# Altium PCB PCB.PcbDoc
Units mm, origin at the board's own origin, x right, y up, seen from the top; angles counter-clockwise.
Board outline 90 x 70 mm, 2 copper layers (Top Layer, Bottom Layer); 87 components, 38 nets, 231 pads, 138 vias.
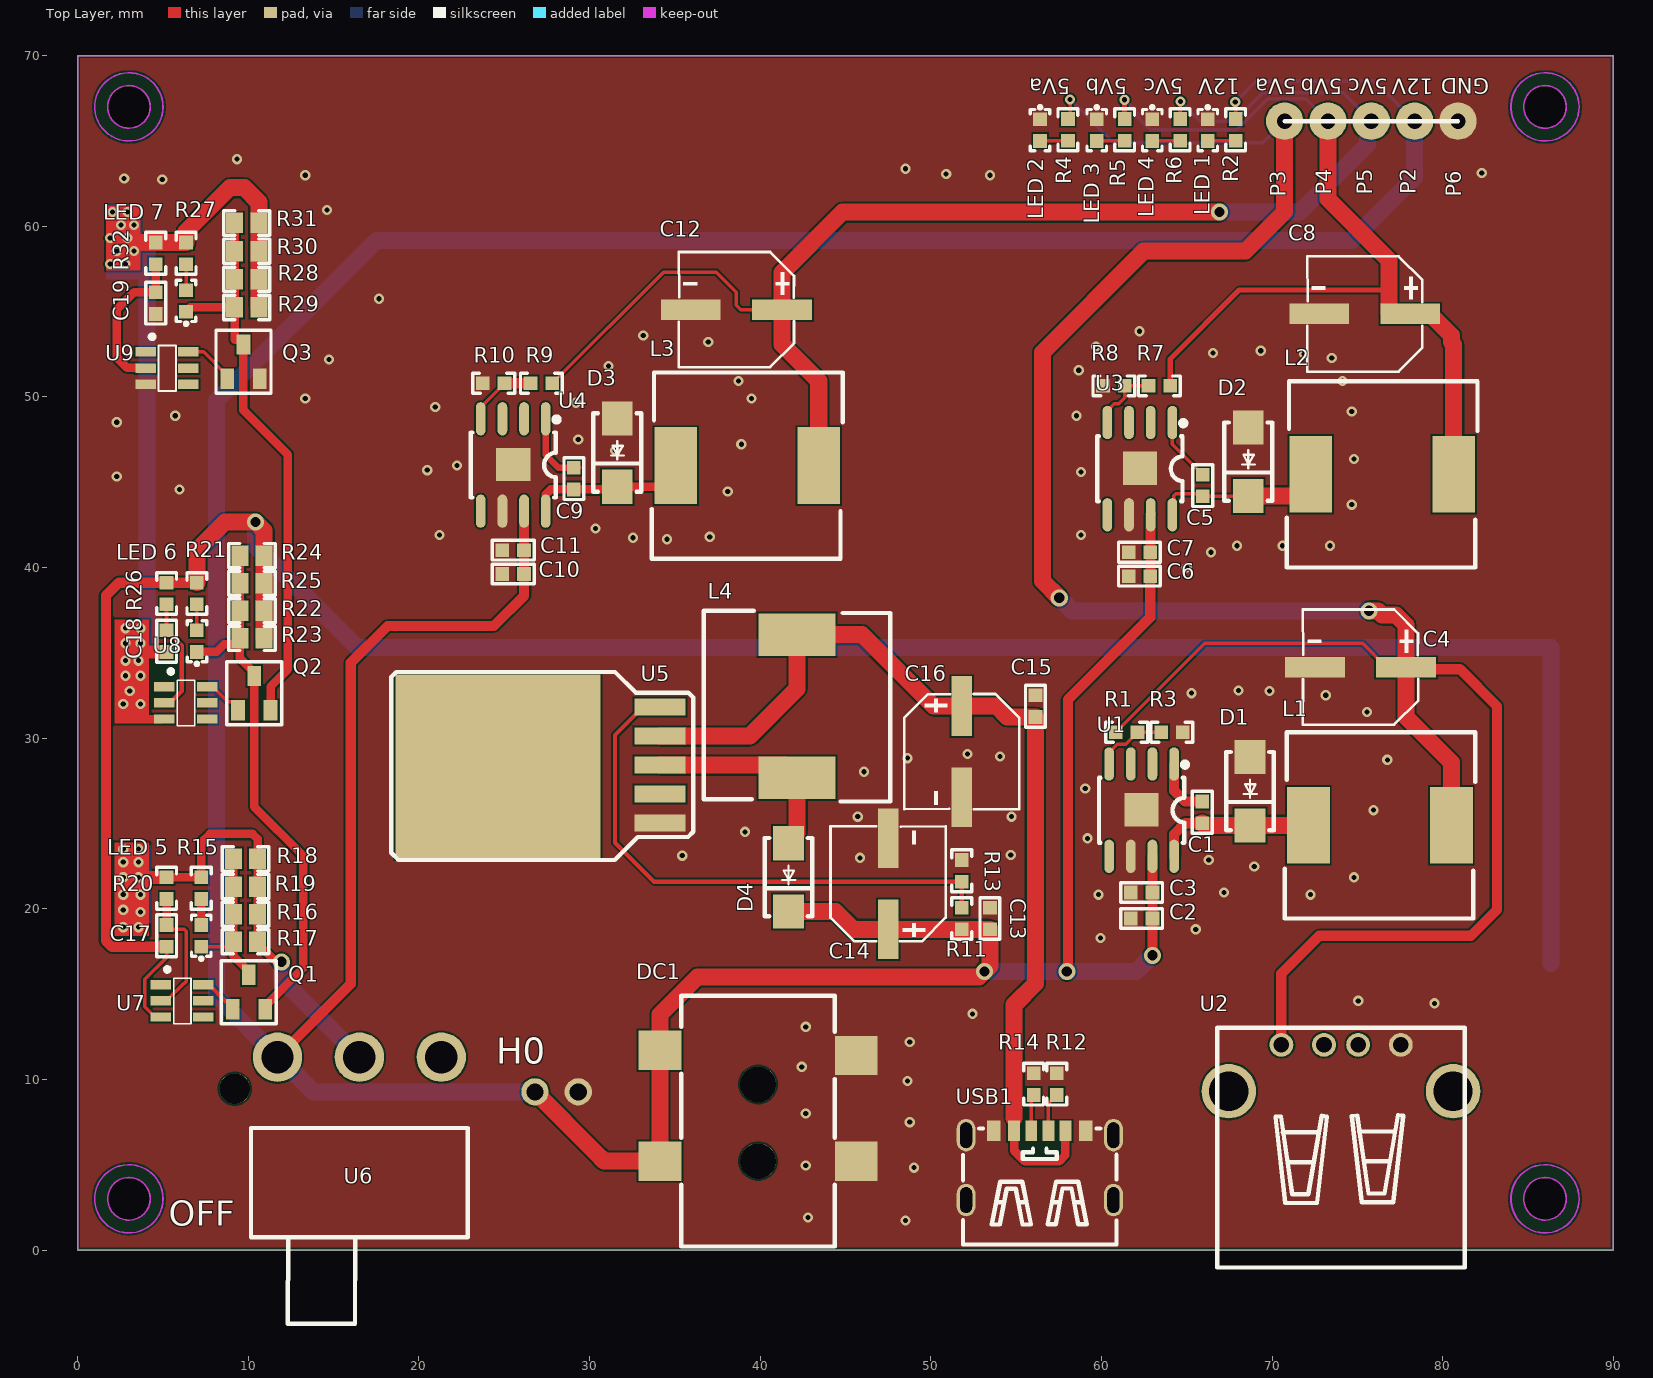
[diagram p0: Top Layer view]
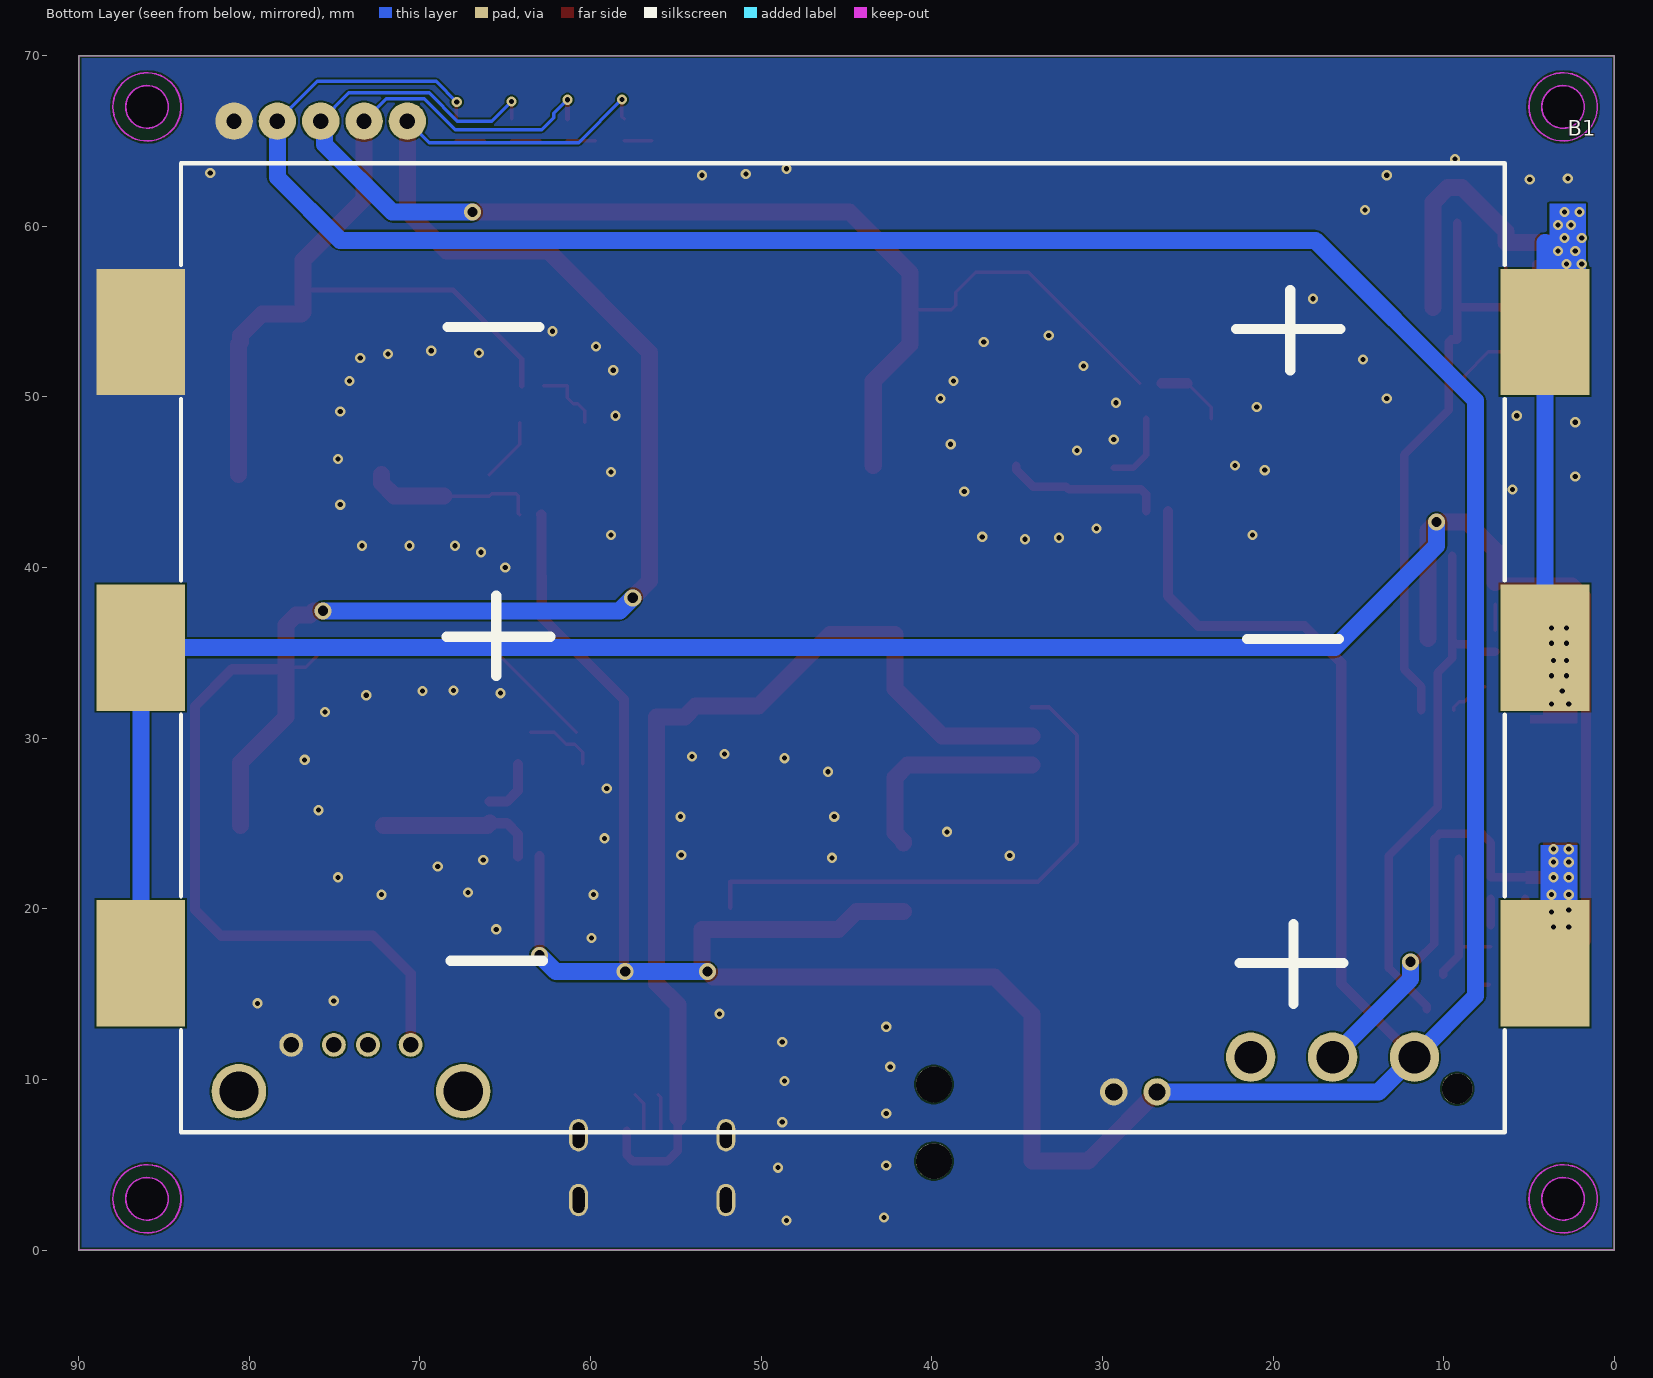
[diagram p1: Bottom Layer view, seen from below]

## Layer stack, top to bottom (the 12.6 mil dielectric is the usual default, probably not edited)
Top Solder: solder mask 0.0102, Solder Resist, Dk 3.5
Top Layer: signal copper 0.0356
Dielectric 1: dielectric 0.32, FR-4, Dk 4.8
Bottom Layer: signal copper 0.0356
Bottom Solder: solder mask 0.0102, Solder Resist, Dk 3.5

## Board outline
0,0 0,70 90,70 90,0
cut-out: 84.75,3 ccw(c86,3) 86,1.75 ccw(c86,3) 87.25,3 ccw(c86,3) 86,4.25 ccw(c86,3)
cut-out: 1.75,3 ccw(c3,3) 3,1.75 ccw(c3,3) 4.25,3 ccw(c3,3) 3,4.25 ccw(c3,3)
cut-out: 84.75,67 ccw(c86,67) 86,65.75 ccw(c86,67) 87.25,67 ccw(c86,67) 86,68.25 ccw(c86,67)
cut-out: 3,65.75 cw(c3,67) 1.75,67 cw(c3,67) 3,68.25 cw(c3,67) 4.25,67 cw(c3,67)

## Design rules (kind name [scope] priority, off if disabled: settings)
Clearance [All] p1: gap=0.1 ignorepadtopadclearanceinfootprint=FALSE except(0: Arc-Hole Track-Hole SMDPad-Hole THPad-Hole Via-Hole Fill-Hole Poly-Hole Region-Hole Text-Hole; 0.102: Arc-Arc Arc-Track Arc-SMDPad Arc-THPad Track-Track Track-SMDPad Track-THPad SMDPad-SMDPad SMDPad-THPad THPad-THPad; 0.127: Arc-Via Track-Via SMDPad-Via SMDPad-Text THPad-Via Via-Via; 0.254: Arc-Text Track-Text THPad-Text Via-Text Fill-Text Poly-Text Region-Text Text-Text)
ComponentClearance [All] p1 off: gap=0 collisioncheckmode=3 verticalgap=0 showdistances=TRUE
HoleSize [All] p1: absolutevalues=TRUE maxlimit=30 minlimit=0.025 maxpercent=80.000 minpercent=20.000
HoleToHoleClearance [All] p1: gap=0.152 allowstackedmicrovias=TRUE
MinimumSolderMaskSliver [All] p1: minsoldermaskwidth=0
PlaneClearance [All] p1: clearance=0.254
PlaneConnect [All] p1: planeconnectstyle=Direct reliefexpansion=0.508 reliefentries=4 reliefconductorwidth=0.254 reliefairgap=0.254
PolygonConnect [All] p1: connectstyle=Direct reliefconductorwidth=0.254 reliefentries=4 polygonreliefangle="90 Angle" airgapwidth=0.254
RoutingVias [All] p1: holewidth=0.711 width=1.27 viastyle="Through Hole" minholewidth=0.3 minwidth=0.5 maxholewidth=30 maxwidth=30
SilkToSilkClearance [All] p1: silktosilkclearance=0
SilkToSolderMaskClearance [IsPad] p1: minsilkscreentomaskgap=0 clearancetoexposedcopper=TRUE
SolderMaskExpansion [All] p1: expansion=0.102 istentingtop=FALSE
Width [All] p1: maxlimit=5 minlimit=0.1 preferedwidth=0.254
22 further rules are at their usual default settings.

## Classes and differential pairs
component class Sheet1-MCU: C1 C2 C3 C4 C5 C6 C7 C8 C9 C10 C11 C12 C13 C14 C15 C16 D1 D2 D3 D4 DC1 H0 L1 L2 L3 L4 "LED 1" "LED 2" "LED 3" "LED 4" P2 P3 P4 P5 P6 R1 R2 R3 R4 R5 R6 R7 R8 R9 R10 R11 R12 R13 R14 U1 U2 U3 U4 U5 U6 USB1
component class Sheet2-bms: B1 C17 C18 C19 "LED 5" "LED 6" "LED 7" Q1 Q2 Q3 R15 R16 R17 R18 R19 R20 R21 R22 R23 R24 R25 R26 R27 R28 R29 R30 R31 R32 U7 U8 U9

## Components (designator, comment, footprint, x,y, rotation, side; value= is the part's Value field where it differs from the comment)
B1 "18650-box-3S" BAT-SMD_BH-18650-B5BA016 45.212,35.306 r0 bottom locked
C1 "0.01uf" CC1608-0603 65.913,25.654 r270 top
C2 "4.7uF 50V" CC1608-0603 62.357,19.431 r180 top
C3 "4.7uF 50V" CC1608-0603 62.357,20.955 r180 top
C4 "16V 220uF" CAP-SMD_D6.3 75.184,34.163 r180 top
C5 "0.01uf" CC1608-0603 65.938,44.806 r270 top
C6 "4.7uF 50V" CC1608-0603 62.23,39.497 r180 top
C7 "4.7uF 50V" CC1608-0603 62.23,40.894 r180 top
C8 "16V 220uF" CAP-SMD_D6.3 75.441,54.864 r180 top
C9 "0.01uf" CC1608-0603 29.083,45.212 r270 top
C10 "4.7uF 50V" CC1608-0603 25.527,39.624 r180 top
C11 "4.7uF 50V" CC1608-0603 25.527,41.021 r180 top
C12 "16V 220uF" CAP-SMD_D6.3 38.608,55.118 r180 top
C13 "100NF" CC1608-0603 53.467,19.431 r270 top
C14 "16V 220uF" CAP-SMD_D6.3 47.498,21.463 r90 top
C15 "100NF" CC1608-0603 56.134,31.877 r270 top
C16 "16V 220uF" CAP-SMD_D6.3 51.816,29.21 r270 top
C17 "100NF" CC1608-0603 5.207,18.415 r90 top
C18 "100NF" CC1608-0603 5.207,35.687 r90 top
C19 "100NF" CC1608-0603 4.572,55.499 r90 top
D1 "B340A" "DO-214 AA" 68.707,26.892 r90 top
D2 "B340A" "DO-214 AA" 68.605,46.203 r90 top
D3 "B340A" "DO-214 AA" 31.623,46.736 r90 top
D4 "SS56" "DO-214 AA" 41.656,21.844 r90 top
DC1 "DC-2.1" DC-IN-SMD_DC-050-25A 39.878,8.457 r180 top
H0 "Header_2P_Curved" Header_2_54_2PW 26.797,9.271 r0 top
L1 "22UH" Inductor-1040 72.136,24.892 r90 top
L2 "22UH" Inductor-1040 72.263,45.466 r90 top
L3 "22UH" Inductor-1040 35.052,45.974 r90 top
L4 "47UH" Inductor-1040 42.164,36.068 r0 top
"LED 1" "LED 0603" "LED 0603" 66.232,65.64 r90 top
"LED 2" "LED 0603" "LED 0603" 56.404,65.64 r90 top
"LED 3" "LED 0603" "LED 0603" 59.726,65.64 r90 top
"LED 4" "LED 0603" "LED 0603" 62.979,65.64 r90 top
"LED 5" "LED 0603" "LED 0603" 7.239,18.415 r270 top
"LED 6" "LED 0603" "LED 0603" 6.985,35.687 r270 top
"LED 7" "LED 0603" "LED 0603" 6.35,55.626 r270 top
P2 "pogopin" pogopin 78.359,66.167 r0 top
P3 "pogopin" pogopin 70.739,66.167 r0 top
P4 "pogopin" pogopin 73.279,66.167 r0 top
P5 "pogopin" pogopin 75.819,66.167 r0 top
P6 "pogopin" pogopin 80.899,66.167 r0 top
Q1 "SI2302" SOT-23 9.083,14.109 r0 top
Q2 "SI2302" SOT-23 9.398,31.623 r0 top
Q3 "SI2302" SOT-23 8.763,51.054 r0 top
R1 "10K 1%" CR1608-0603 61.484,30.353 r180 top
R2 "1K" CR1608-0603 67.867,65.659 r270 top
R3 "3.24K 1%" CR1608-0603 64.135,30.353 r180 top
R4 "1K" CR1608-0603 58.039,65.659 r270 top
R5 "1K" CR1608-0603 61.362,65.659 r270 top
R6 "1K" CR1608-0603 64.615,65.659 r270 top
R7 "10K 1%" CR1608-0603 63.398,50.648 r0 top
R8 "3.24K 1%" CR1608-0603 60.731,50.648 r0 top
R9 "10K 1%" CR1608-0603 27.178,50.8 r0 top
R10 "3.24K 1%" CR1608-0603 24.384,50.8 r0 top
R11 "88.7K" CR1608-0603 51.816,19.431 r270 top
R12 "5.1K" CR1608-0603 57.389,9.724 r90 top
R13 "10K" CR1608-0603 51.816,22.225 r270 top
R14 "5.1K" CR1608-0603 56.028,9.724 r90 top
R15 "1K" CR1608-0603 7.239,21.209 r270 top
R16 "120R 1/8W" CR2012-0805 9.837,19.684 r180 top
R17 "120R 1/8W" CR2012-0805 9.837,18.065 r180 top
R18 "120R 1/8W" CR2012-0805 9.837,22.922 r180 top
R19 "120R 1/8W" CR2012-0805 9.837,21.303 r180 top
R20 "100R" CR1608-0603 5.207,21.209 r270 top
R21 "1K" CR1608-0603 6.985,38.481 r270 top
R22 "120R 1/8W" CR2012-0805 10.218,37.464 r180 top
R23 "120R 1/8W" CR2012-0805 10.218,35.845 r180 top
R24 "120R 1/8W" CR2012-0805 10.218,40.702 r180 top
R25 "120R 1/8W" CR2012-0805 10.218,39.083 r180 top
R26 "100R" CR1608-0603 5.207,38.481 r270 top
R27 "1K" CR1608-0603 6.35,58.42 r270 top
R28 "120R 1/8W" CR2012-0805 9.906,56.896 r180 top
R29 "120R 1/8W" CR2012-0805 9.906,55.245 r180 top
R30 "120R 1/8W" CR2012-0805 9.906,58.547 r180 top
R31 "120R 1/8W" CR2012-0805 9.906,60.198 r180 top
R32 "100R" CR1608-0603 4.572,58.42 r270 top
U1 "TPS5430DDAR" SOIC-8-E 62.357,25.781 r180 top
U2 "USB2.0-A" USB2.0-A 74.041,10.668 r0 top
U3 "TPS5430DDAR" SOIC-8-E 62.255,45.796 r180 top
U4 "TPS5430DDAR" SOIC-8-E 25.527,46.012 r180 top
U5 "XL6019E1" TO-263-5 34.136,25.019 r90 top
U6 "HX SS12D10G4" SW-TH_3P-SS12D06 16.51,11.303 r0 top
U7 "HY2213-BB3A" SOT23-6 6.136,14.666 r270 top
U8 "HY2213-BB3A" SOT23-6 6.35,32.131 r270 top
U9 "HY2213-BB3A" SOT23-6 5.247,51.75 r270 top
USB1 "TYPE_C_SMD_6P" TYPE-C-SMD_TYPE-C-6P 56.388,4.953 r0 top

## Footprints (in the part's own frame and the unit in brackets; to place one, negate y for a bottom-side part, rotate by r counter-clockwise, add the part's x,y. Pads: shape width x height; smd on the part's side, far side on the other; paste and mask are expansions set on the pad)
BAT-SMD_BH-18650-B5BA016 [mm]
  rect 5.2x7.4 smd paste+0 mask+0.051: 1(-41.15,18.5) 2(41.15,18.5) 3(-41.15,0) 4(41.15,0) 5(-41.15,-18.5) 6(41.15,-18.5)
  round 1.8 hole 1.8 unplated paste+0: ""(-36,25.85)
  silkscreen extent -38.8,-28.4 38.8,28.4, body extent -42.95,-29.21 43.12,29.73, height 18.7
CAP-SMD_D6.3 [mm] "直径6.3mm固态电容"
  rect 3.5x1.2 smd paste+0 mask+0.051: 1(-2.67,0) 2(2.67,0)
  silkscreen extent -3.38,-3.38 3.38,3.38, body extent -3.65,-3.3 3.65,3.3, height 5.9
CC1608-0603 [mm]
  rect 0.8x0.8 smd: 1(-0.635,0) 2(0.635,0)
  silkscreen extent -1.23,-0.58 1.23,0.58, body extent -0.8,-0.4 0.8,0.4, height 0.3
CR1608-0603 [mm]
  rect 0.8x0.8 smd: 1(-0.635,0) 2(0.635,0)
  silkscreen extent -1.23,-0.58 1.23,0.58, body extent -0.8,-0.4 0.8,0.4, height 0.45
CR2012-0805 [mm]
  rect 1x1.2 smd: 1(-0.71,0) 2(0.71,0)
  silkscreen extent -1.35,-0.71 1.35,0.71, body extent -1,-0.63 1,0.63, height 0.55
DC-IN-SMD_DC-050-25A [mm]
  rect 2.5x2.3 smd: 1(5.75,3.25) 1(5.75,-3.25) 2(-5.75,3.25) 3(-5.75,-2.95)
  round 2.1 hole 2.1 unplated: ""(0,3.25) ""(0,-1.25)
  silkscreen extent -4.5,-6.45 4.5,8.25, body extent -6.28,-6.57 6.28,8.13, height 10.94
"DO-214 AA" [mm] "SMB"
  rect 2x1.8 smd: 1(-2,0) 2(2,0)
  silkscreen extent -2.3,-1.4 2.3,1.4, body extent -2.83,-1.8 2.57,1.8, height 2.4
Header_2_54_2PW [mm] "弯的排针"
  round 1.6 hole 1: 1(0,0) 2(2.54,0)
  body extent -2.52,-7.47 5.18,0.38, height 5.8
Inductor-1040 [mm]
  rect 4.5x2.5 smd: 1(0,0) 2(0,-8.382)
  silkscreen extent -5.46,-9.78 5.46,1.4, body extent -5,-9.39 5,1.01, height 3.9
"LED 0603" [mm]
  rect 0.8x0.8 smd: 1(-0.635,0) 2(0.635,0)
  silkscreen extent -1.21,-0.57 1.4,0.57, body extent -0.8,-0.4 0.8,0.4, height 0.6
pogopin [mm]
  round 2.2 hole 0.9: 1(0,0)
  body extent -1,-1 1,1, height 10
SOIC-8-E [mil]
  oval 22.38x76.78 smd paste+0 mask+2: 1(-75,-106.5) 2(-25,-106.5) 3(25,-106.5) 4(75,-106.5) 5(75,106.5) 6(25,106.5) 7(-25,106.5) 8(-75,106.5)
  rect 78.74x76.78 smd paste+0 mask+2: 9(0,-1)
  silkscreen extent -106,-111 98,75, body extent -98,-125 98,120, height 69
SOT23-6 [mm]
  rect 0.55x1.2 smd: 1(-0.889,-1.27) 2(0.061,-1.27) 3(1.011,-1.27) 4(1.011,1.23) 5(0.061,1.23) 6(-0.889,1.23)
  silkscreen extent -1.9,-1.02 1.4,0.51, body extent -1.39,-1.4 1.51,1.4, height 1.45
SOT-23 [mm]
  rect 0.8x1.2 smd: 1(0,0) 2(1.905,0) 3(0.95,2.02)
  silkscreen extent -0.66,-0.84 2.57,2.84, body extent -0.61,-0.23 2.39,2.27, height 1.05
SW-TH_3P-SS12D06 [mm]
  round 2.9 hole 1.9 paste+0 mask+0.051: 1(-4.8,0) 2(0,0) 3(4.8,0)
  silkscreen extent -6.35,-15.62 6.35,-4.15, body extent -6.35,-15.68 6.35,-4.19, height 6.7
TO-263-5 [mm]
  rect 1x3 smd: 1(0,0) 2(1.7,0) 3(3.4,0) 4(5.1,0) 5(6.8,0)
  rect 10.8x12 smd: 6(3.302,9.498)
  silkscreen extent -2.16,-1.94 8.86,15.76, body extent -1.63,-0.74 8.37,14.93, height 4.88
TYPE-C-SMD_TYPE-C-6P [mm]
  oval 1.1x1.9 hole 0.7 slot 1.5 at 90 deg paste+0 mask+0.051: 7(-4.32,-2.025) 7(-4.32,1.775) 7(4.32,-2.025) 7(4.32,1.775)
  rect 0.7x1.2 smd paste-100 mask+0.051: A5(-0.5,2.025) A9(1.5,2.025) B5(0.5,2.025) B9(-1.5,2.025)
  rect 0.8x1.2 smd paste-100 mask+0.051: A12(2.7,2.025) B12(-2.7,2.025)
  silkscreen extent -4.5,-4.63 4.5,2.18, body extent -4.44,-4.47 4.49,2.43, height 3.18
USB2.0-A [mm]
  round 3.2 hole 2.3: 0(-6.571,-1.359) 0(6.571,-1.359)
  round 1.4 hole 0.92: 1(-3.492,1.359) 2(-0.993,1.359) 3(1.008,1.359) 4(3.508,1.359)
  silkscreen extent -7.25,-11.7 7.26,2.37, body extent -7.85,-11.28 7.95,2.42, height 6.95

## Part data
B1: "18650贴片电池盒"
C1 C2 C3 C5 C6 C7 C9 C10 C11: library part "Chip capacitor", "贴片电容"
C4 C8 C12 C14 C16: library part "Cap ECAP SMD", "铝点解电容", BOM_Manufacturer=PANASONIC, BOM_Manufacturer Part=EEEFP1C681AP
C13 C15 C17 C18 C19: library part "Cap Chip 0603", "0603封装的电容"
D1 D2 D3: "40V 3A 550mV@3A", BOM_JLCPCB Part Class="Extended Part", BOM_Manufacturer=MDD
D4: library part SS34, "肖特基二极管"
DC1: library part DC-050, "DC贴片插座", BOM_JLCPCB Part Class="Extended Part", BOM_Manufacturer=韩国韩荣, BOM_Manufacturer Part=DC-050-25A
H0: "弯的2P排针"
L1 L2 L3 L4: library part Inductor-1040, "1040封装 一体成型 贴片 功率电感"
P2 P3 P4 P5 P6: "插板式顶针 连接器弹簧天线插针SMT触点测试铜针双弹贴片式"
Q1 Q2 Q3: "N沟道  / 漏源电压(Vdss) 20V  / 连续漏极电流(Id) 2.8A  / 功率(Pd) 900mW  / 导通电阻(RDS(on)@Vgs,Id) 55mΩ@4.5V,2.8A  / 阈值电压(Vgs(th)@Id) 1.2V@250uA  / 输入电容(Ciss@Vds) 260pF@10V", JLCPCB Part Class="Extended Part", Manufacturer=TWGMC(台湾迪嘉), Manufacturer Part=SI2306
R1 R3 R7 R8 R9 R10: library part "Chip resistor", "贴片电阻"
R2 R4 R5 R6 R11 R12 R13 R14 R15 R20 R21 R26 R27 R32: library part "Resistor Chip 0603", "0603封装电阻"
R16 R17 R18 R19 R22 R23 R24 R25 R28 R29 R30 R31: library part "Resistor Chip 0805", "0805封装电阻"
U1 U3 U4: "宽电压DCDC降压IC"
U2: "USB母座"
U5: "升压芯片 5A最大输出"
U6: library part SW-TH_3P-SS12D06, BOM_JLCPCB Part Class="Extended Part", BOM_Manufacturer=hanxia(韩下)
U7 U8 U9: "HY2213-BB3A的原理很简单，它就是监测每节电池的电压，当其超过4.2V后，就开启一个放电回路，以减少此节电池的充电电流。具体放电电流可以通过电阻自定义。"
USB1: JLCPCB Part Class="Extended Part", Manufacturer=null

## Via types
v1: diameter 0.6, hole 0.3, Top Layer to Bottom Layer, tented both sides, 130 vias
v2: diameter 1, hole 0.6, Top Layer to Bottom Layer, tented both sides, 8 vias

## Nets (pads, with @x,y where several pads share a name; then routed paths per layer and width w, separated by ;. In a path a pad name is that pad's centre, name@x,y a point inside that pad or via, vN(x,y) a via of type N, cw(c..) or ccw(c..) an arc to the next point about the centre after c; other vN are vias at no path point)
5V_1: C4.1 L1.2 P3.1 R1.2 R4.1 U2.1 | length 143.2
  Top Layer w0.2: R4.1 58.166,66.421 v1(58.166,67.437) ; R1.2 66.056,35.56 75.307,35.56 76.704,34.163 C4.1
  Top Layer w0.6: U2.1 70.549,16.192 72.771,18.415 81.661,18.415 83.185,19.939 83.185,31.877 81.026,34.036 77.981,34.036 C4.1
  Top Layer w1: v2(57.531,38.227) 56.548,39.21 56.548,52.611 62.484,58.547 68.453,58.547 70.739,60.833 P3.1 ; v2(75.692,37.465) 76.2,37.465 76.454,37.211 77.268,37.211 77.854,36.625 C4.1 77.854,31.239 80.518,28.575 L1.2
  Bottom Layer w0.2: v1(58.166,67.437) 60.706,64.897 69.469,64.897 P3.1
  Bottom Layer w1: v2(57.531,38.227) 58.293,37.465 v2(75.692,37.465)
5V_2: C8.1 L2.2 P4.1 R5.1 R7.2 | length 56.5
  Top Layer w0.3: R5.1 v1(61.362,67.416) ; R7.2 64.033,52.222 68.072,56.261 76.607,56.261 76.861,56.007
  Top Layer w1: P4.1 73.279,61.595 76.861,58.013 76.861,56.007 76.861,54.964 76.961,54.864 C8.1 79.261,54.864 80.518,53.607 80.518,53.213 80.645,53.086 L2.2
  Bottom Layer w0.2: v1(61.362,67.416) 62.152,66.626 62.152,66.372 62.865,65.659 67.945,65.659 69.755,67.469 71.977,67.469 P4.1
5V_3: C12.1 L3.2 P5.1 R6.1 R9.2 | length 82.7
  Top Layer w0.2: R9.2 34.333,57.32 37.422,57.32 38.608,56.134 38.608,55.372 38.862,55.118 C12.1 ; R6.1 64.615,67.282 v1(64.643,67.31)
  Top Layer w1: L3.2 43.434,50.927 41.278,53.083 C12.1 41.278,57.28 44.831,60.833 v2(66.929,60.833)
  Bottom Layer w0.2: v1(64.643,67.31) 65.786,66.167 67.818,66.167 69.469,67.818 74.168,67.818 P5.1
  Bottom Layer w1: v2(66.929,60.833) 71.628,60.833 75.589,64.794 75.589,65.937 P5.1
12.33V: C2.1 C3.1 C6.1 C7.1 C10.1 C11.1 C13.2 C14.1 D4.1 DC1.1 H0.1 P2.1 R2.1 R11.2 U1.7 U3.7 U4.7 U6.1 | length 287
  Top Layer w0.2: v1@67.818,67.31 67.867,67.261 R2.1
  Top Layer w0.6: U6.1 16.002,15.595 16.002,34.417 18.161,36.576 24.384,36.576 26.162,38.354 C10.1 C11.1 U4.7 ; v2@57.912,16.256 58.039,16.383 58.039,32.258 62.865,37.084 C6.1 62.878,39.51 62.878,43.078 U3.7 ; v2(62.992,17.272) C2.1 C3.1 U1.7
  Top Layer w1: H0.1 30.353,5.715 30.861,5.207 31.623,5.207 34.128,5.207 34.128,11.707 34.128,13.808 36.322,16.002 52.832,16.002 v2(53.149,16.319) 53.467,16.637 C13.2 R11.2 47.501,18.796 C14.1 45.469,18.793 44.418,19.844 D4.1
  Bottom Layer w0.2: v1(67.843,67.285) 69.058,68.501 76.025,68.501 P2.1
  Bottom Layer w1: H0.1 26.777,9.251 13.83,9.251 11.779,11.303 U6.1 8.128,14.885 8.128,49.784 17.526,59.182 74.676,59.182 78.359,62.865 P2.1 ; v2(53.149,16.319) 62.039,16.319 v2(62.992,17.272)
  other v2: 57.975,16.319
BANK+: B1.1 R15.1 R16.1 R17.1 R18.1 R19.1 R20.1 U6.2 | length 23
  Top Layer w0.5: R20.1 R15.1 7.239,23.876 7.747,24.384 10.253,24.384 10.546,24.091 R18.1 R19.1 R16.1 R17.1 10.546,17.965 11.493,17.018 v2@11.811,17.018
  Bottom Layer w1: v2(11.938,16.891) 11.938,15.875 U6.2
  other v1: 2.667,18.923 3.556,18.923 3.683,19.812 2.667,19.939 2.667,20.828 3.683,20.828 2.667,21.844 3.556,21.844 2.667,22.733 3.556,22.733 2.667,23.495 3.556,23.495
GND: "LED 1.2" "LED 2.2" "LED 3.2" "LED 4.2" B1.6 C2.2 C3.2 C4.2 C6.2 C7.2 C8.2 C10.2 C11.2 C12.2 C13.1 C14.2 C15.1 C16.2 C19.1 D1.2 D2.2 D3.2 DC1.2 DC1.3 H0.2 P6.1 Q3.2 R3.1 R8.1 R10.1 R12.2 R13.1 R14.2 U1.6 U1.9 U2.4 U3.6 U3.9 U4.6 U4.9 U5.1 U9.3 USB1.7 USB1.A12 USB1.B12
  other v1: 48.526,1.723 42.799,1.905 49.022,4.826 42.672,4.953 48.768,7.493 42.672,8.001 48.641,9.906 42.435,10.735 48.768,12.192 42.672,13.081 52.451,13.843 79.532,14.456 75.057,14.605 59.944,18.288 65.532,18.796 59.827,20.829 72.263,20.828 67.183,20.955 74.803,21.844 68.961,22.479 66.294,22.86 45.847,22.987 35.433,23.114 54.686,23.153 59.182,24.13 39.116,24.511 45.72,25.4 54.737,25.4 75.946,25.781 59.055,27.051 46.086,28.03 76.761,28.729 48.641,28.829 54.062,28.918 52.153,29.069 75.57,31.526 73.152,32.512 65.278,32.639 69.85,32.766 68.029,32.792 65.006,40.009 66.421,40.894 67.945,41.275 70.612,41.275 73.406,41.275 34.544,41.656 32.544,41.744 37.045,41.8 21.209,41.91 58.801,41.91 30.353,42.291 74.676,43.688 38.1,44.45 5.969,44.577 2.286,45.339 58.801,45.593 20.485,45.708 22.225,45.974 74.803,46.355 31.496,46.863 38.897,47.227 29.337,47.498 2.286,48.514 5.715,48.895 58.547,48.895 74.676,49.149 20.955,49.403 29.21,49.657 13.335,49.911 39.497,49.911 38.735,50.927 74.137,50.93 58.674,51.562 31.115,51.816 14.732,52.197 73.505,52.288 71.87,52.519 66.548,52.578 69.342,52.705 59.69,52.959 36.957,53.213 33.147,53.594 62.23,53.848 17.653,55.753 14.605,60.96 4.953,62.738 2.721,62.806 13.335,62.992 53.467,62.992 50.901,63.068 82.296,63.119 48.514,63.373 9.334,63.935
NetB1_2: B1.2 B1.4 C17.1 R21.1 R22.1 R23.1 R24.1 R25.1 R26.1 U7.3 | length 146.2
  Top Layer w0.2: U7.3 4.541,13.655 3.937,14.259 3.937,15.875 5.207,17.145 C17.1
  Top Layer w0.6: C17.1 2.002,17.78 1.651,18.131 1.651,38.354 2.413,39.116 R26.1 R21.1
  Top Layer w1: R21.1 6.985,41.021 8.636,42.672 v2(10.414,42.672) 10.927,42.159 R25.1 R22.1 R23.1
  Bottom Layer w1: v2(10.414,42.672) 10.414,41.275 16.383,35.306 B1.4 B1.2
NetB1_3: B1.3 B1.5 C18.1 R27.1 R28.1 R29.1 R30.1 R31.1 R32.1 U8.3 | length 39.8
  Top Layer w1: v1@2.794,59.055 R32.1 R27.1 6.35,59.69 8.931,62.271 9.76,62.271 10.616,61.416 R31.1 R30.1 R28.1 R29.1
  Bottom Layer w1: B1.3 B1.5 4.062,59.053 4.064,59.055
  other v1: 2.667,32.004 3.683,32.004 3.048,32.766 2.794,33.655 3.683,33.655 2.794,34.544 3.556,34.544 2.794,35.56 3.683,35.56 2.794,36.449 3.683,36.449 1.905,57.785 2.794,57.785 2.286,58.547 3.302,58.547 1.905,59.309 2.921,59.309 2.54,60.071 3.302,60.071 2.032,60.833 2.921,60.833
NetC1_1: C1.1 U1.1 | length 3.5
  Top Layer w0.6: U1.1 64.262,26.924 64.897,26.289 C1.1
NetC1_2: C1.2 D1.1 L1.1 U1.8 | length 9.5
  Top Layer w0.6: U1.8 64.262,24.384 64.897,25.019 C1.2
  Top Layer w1: C1.2 66.04,24.892 D1.1 L1.1
NetC5_1: C5.1 U3.1 | length 3.8
  Top Layer w0.2: U3.1 64.16,47.219 C5.1
NetC5_2: C5.2 D2.1 L2.1 U3.8 | length 10.1
  Top Layer w0.2: U3.8 64.231,43.162 64.231,44.206 64.348,44.323 65.786,44.323 C5.2 68.573,44.171 D2.1
  Top Layer w1: D2.1 71.513,44.203 72.263,44.953 L2.1
NetC9_1: C9.1 U4.1 | length 4.3
  Top Layer w0.4: U4.1 27.432,46.609 28.194,45.847 C9.1@29.337,45.847
NetC9_2: C9.2 D3.1 L3.1 U4.8 | length 9.4
  Top Layer w0.5: U4.8 27.432,44.284 27.725,44.577 29.337,44.577 31.972,44.577 32.131,44.736 34.052,44.736 35.052,45.736 L3.1
NetC17_2: C17.2 R20.2 U7.2 | length 7.7
  Top Layer w0.2: U7.2 5.191,14.605 6.207,15.621 6.233,15.621 6.35,15.738 6.35,18.679 6.233,18.796 5.461,18.796 C17.2
  Top Layer w0.5: C17.2 R20.2
NetC18_2: C18.2 R26.2 U8.2 | length 6.8
  Top Layer w0.254: U8.2 5.405,32.07 6.096,32.761 6.096,35.433 C18.2 R26.2
NetC19_2: C19.2 R32.2 U9.2 | length 9.1
  Top Layer w0.5: U9.2 3.952,51.714 2.896,51.714 2.286,52.324 2.286,55.118 3.302,56.134 C19.2 R32.2
NetD4_2: D4.2 L4.2 U5.3 | length 12.4
  Top Layer w1: U5.3 41.431,28.419 L4.2 42.164,24.452 41.656,23.944 D4.2
"NetLED 1_1": "LED 1.1" R2.2 | length 1.6
  Top Layer w0.2: 66.232,65.005 67.848,65.005 R2.2
"NetLED 2_1": "LED 2.1" R4.2 | length 1.6
  Top Layer w0.2: 56.404,65.005 58.02,65.005 R4.2
"NetLED 3_1": "LED 3.1" R5.2 | length 1.6
  Top Layer w0.2: 59.726,65.005 61.343,65.005 R5.2
"NetLED 4_1": "LED 4.1" R6.2 | length 1.6
  Top Layer w0.2: 62.979,65.005 64.596,65.005 R6.2
"NetLED 5_1": "LED 5.1" R15.2 | length 1.5
  Top Layer w0.5: 7.239,19.05 R15.2
"NetLED 5_2": "LED 5.2" Q1.3 R16.2 R17.2 R18.2 R19.2 | length 9.2
  Top Layer w0.2: 7.239,17.78 8.842,17.78 R17.2
  Top Layer w0.5: R18.2 R19.2 R16.2 R17.2 9.127,17.235 10.033,16.329 Q1.3
"NetLED 6_1": "LED 6.1" R21.2 | length 1.5
  Top Layer w0.2: 6.985,36.322 R21.2
"NetLED 6_2": "LED 6.2" Q1.2 Q2.3 R22.2 R23.2 R24.2 R25.2 | length 31.9
  Top Layer w0.5: 6.985,35.052 8.135,35.052 8.578,35.495 9.258,35.495 R23.2@9.508,35.745 ; R24.2 R25.2 R22.2 R23.2 R23.2@9.508,35.745 ; Q1.2 10.988,14.309 13.208,16.529 13.208,23.114 10.348,25.974 Q2.3 10.348,33.843 9.508,34.683 R23.2@9.508,35.745
"NetLED 7_1": "LED 7.1" R27.2 | length 1.5
  Top Layer w0.2: 6.35,56.261 R27.2
"NetLED 7_2": "LED 7.2" Q2.2 Q3.3 R28.2 R29.2 R30.2 R31.2 | length 33.5
  Top Layer w0.5: 6.35,54.991 6.604,55.245 R29.2 ; R31.2 R30.2 R28.2 R29.2 ; Q2.2 11.303,33.02 12.319,34.036 12.319,46.609 9.713,49.215 Q3.3 9.713,53.217 9.563,53.367 9.196,53.367 R29.2
NetQ1_1: Q1.1 U7.6 | length 2.4
  Top Layer w0.254: U7.6 7.691,15.555 8.664,14.582 8.81,14.582 9.083,14.309 Q1.1
NetQ2_1: Q2.1 U8.6 | length 2.5
  Top Layer w0.2: U8.6 7.905,33.02 8.802,32.123 9.098,32.123 9.398,31.823 Q2.1
NetQ3_1: Q3.1 U9.6 | length 3.1
  Top Layer w0.2: U9.6 7.378,52.639 8.763,51.254 Q3.1
NetR1_1: R1.1 R3.2 U1.4 | length 4.2
  Top Layer w0.2: U1.4 60.452,29.177 60.925,29.65 61.416,29.65 R1.1 R3.2
NetR7_1: R7.1 R8.2 U3.4 | length 4.1
  Top Layer w0.2: U3.4 60.35,49.192 60.764,49.605 61.024,49.605 61.366,49.948 R8.2 R7.1
NetR9_1: R9.1 R10.2 U4.4 | length 4.2
  Top Layer w0.2: U4.4 23.622,49.403 R10.2
  Top Layer w0.6: R10.2 R9.1
NetR11_1: R11.1 R13.2 U5.5 | length 32.4
  Top Layer w0.254: U5.5 33.136,31.819 31.496,30.179 31.496,23.876 33.782,21.59 R13.2 R11.1
NetR12_1: R12.1 USB1.B5 | length 2.3
  Top Layer w0.2: USB1.B5 56.888,8.587 R12.1
NetR14_1: R14.1 USB1.A5 | length 2.2
  Top Layer w0.2: USB1.A5 55.888,8.948 R14.1
"USB 5V": C15.2 C16.1 L4.1 U5.4 USB1.A9 USB1.B9 | length 59.1
  Top Layer w0.5: 54.888,7.747 USB1.B9 54.888,5.818 55.499,5.207 57.531,5.207 57.888,5.564 USB1.A9
  Top Layer w1: U5.4 39.39,30.119 42.164,32.893 L4.1 45.974,36.068 50.162,31.88 C16.1 53.845,31.88 54.483,31.242 C15.2 56.134,15.621 54.888,14.375 54.888,7.747
pads on no net: B1. DC1. U1.2 U1.3 U1.5 U2.0 U2.2 U2.3 U3.2 U3.3 U3.5 U4.2 U4.3 U4.5 U5.2 U5.6 U6.3 U7.1 U7.4 U7.5 U8.1 U8.4 U8.5 U9.1 U9.4 U9.5

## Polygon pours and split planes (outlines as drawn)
GND on Bottom Layer "GND_L02_P001" (solid, remove dead copper, pour order 1): 0,0 0,70 90,70 90,0
GND on Top Layer "GND_L01_P000" (solid, remove dead copper, pour order 0): 0,0 0,70 90,70 90,0

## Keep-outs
Keep-Out Layer:
  circle w0.1: c86,67 r2
  circle w0.1: c86,3 r2
  circle w0.1: c3,3 r2
  circle w0.1: c3,67 r2
  circle w0.1: c86,67 r1.25
  circle w0.1: c86,3 r1.25
  circle w0.1: c3,3 r1.25
  circle w0.1: c3,67 r1.25
  lines w0.1: 0,0 90,0 90,70 0,70 0,0

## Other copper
Top Layer:
  rectangle net BANK+: 2.159,18.415 4.191,23.876
  rectangle net BANK+: 2.159,21.463 5.207,22.225
  rectangle net NetB1_3: 2.159,30.861 4.191,32.512
  rectangle net NetB1_3: 2.159,30.861 4.953,31.369
  rectangle net NetB1_3: 3.429,34.671 5.207,35.433
  rectangle net NetB1_3: 2.159,31.75 4.191,36.957
  rectangle net NetB1_3: 1.651,57.404 3.683,61.214
Bottom Layer:
  rectangle net BANK+: 2.159,19.177 4.318,23.749
  rectangle net NetB1_3: 1.651,56.896 3.81,61.341

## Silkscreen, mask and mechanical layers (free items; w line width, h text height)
Top Overlay:
  lines w0.254: 70.739,66.167 73.279,66.167 75.819,66.167 78.359,66.167 80.899,66.167
  text "12V" at 68.095,68.948 h1.52 r180
  text "12V" at 79.453,68.948 h1.52 r180
  text "GND" at 82.725,68.962 h1.52 r180
  text "5Va" at 58.166,68.945 h1.52 r180
  text "5Vb" at 61.502,68.945 h1.52 r180
  text "5Vc" at 64.805,68.945 h1.52 r180
  text "5Va" at 71.429,68.945 h1.52 r180
  text "5Vb" at 74.13,68.945 h1.52 r180
  text "5Vc" at 76.799,68.945 h1.52 r180
  text "OFF" at 5.334,0.915 h2.5
Top Solder:
  circle w1: c86,3 r1.5
  circle w1: c86,67 r1.5
  circle w1: c3,67 r1.5
  circle w1: c3,3 r1.5
Bottom Solder:
  circle w1: c86,3 r1.5
  circle w1: c86,67 r1.5
  circle w1: c3,67 r1.5
  circle w1: c3,3 r1.5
